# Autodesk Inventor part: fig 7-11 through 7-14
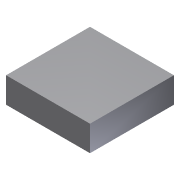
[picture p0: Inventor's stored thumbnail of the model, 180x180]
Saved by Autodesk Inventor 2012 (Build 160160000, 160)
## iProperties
Created: 2009-09
Part Number: fig 7-11 through 7-14
Document SubType Name: Modeling
Designer: Sham
Density: 1 g/cm^3
Material: Default
Author: Sham
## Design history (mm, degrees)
sketch "Sketch1"
  geometry: L1 (-23, 20)-(0, 20); L2 (0, 20)-(0, -3); L3 (0, -3)-(-23, -3); L4 (-23, -3)-(-23, 20)
  constraints: 8 end point, 2 parallel, 1 horizontal, 1 perpendicular
  dimensions: "d2" = 23 distance of L1.start L1.end; "d3" = 23 distance of L3.end L1.start
extrude "Extrusion1" new body sketch "Sketch1" distance "d0" = 7; taper "d1" = 0 deg
body "Solid1"
